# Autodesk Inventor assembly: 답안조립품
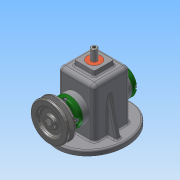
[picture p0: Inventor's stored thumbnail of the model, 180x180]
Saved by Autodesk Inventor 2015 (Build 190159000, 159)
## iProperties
Created: 2017-07
Part Number: 답안조립품
Document SubType Name: Assembly
Designer: owner
Author: owner
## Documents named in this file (14)
- C:\Users\owner\Desktop\470707V1010\답안조립품.iam
- C:\Users\owner\Desktop\470707V1010\본체.ipt
- C:\Users\owner\Desktop\470707V1010\편심축.ipt
- C:\Users\owner\Desktop\470707V1010\링크.ipt
- C:\Users\owner\Desktop\470707V1010\베어링 12 x 32 x 10.ipt
- C:\Users\owner\Desktop\470707V1010\앞커버.ipt
- C:\Users\owner\Desktop\470707V1010\볼트 M4 x 12.ipt
- C:\Users\owner\Desktop\470707V1010\뒤커버.ipt
- C:\Users\owner\Desktop\470707V1010\오일실 12 25 7.ipt
- C:\Users\owner\Desktop\470707V1010\슬라이드.ipt
- C:\Users\owner\Desktop\470707V1010\핀 5 x 18.ipt
- C:\Users\owner\Desktop\470707V1010\부시.ipt
- C:\Users\owner\Desktop\470707V1010\키 4 x 4 x 10.ipt
- C:\Users\owner\Desktop\470707V1010\V벨트풀리.ipt
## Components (2 placed, 2 different names)
1. 핀 5 x 18:1 — 각도:1
2. V벨트풀리:1 — 각도:3
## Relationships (2: Angle 2)
- 각도:1 [Angle]: 핀 5 x 18:1
- 각도:3 [Angle]: V벨트풀리:1
